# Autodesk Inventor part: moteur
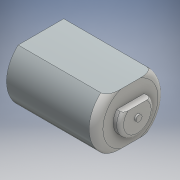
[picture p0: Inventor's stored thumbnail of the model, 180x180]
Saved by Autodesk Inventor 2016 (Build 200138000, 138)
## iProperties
Created: 2018-03
Part Number: moteur
Material: Générique
Document SubType Name: Modeling
Designer: Bruno
Density: 1 g/cm^3
Appearance: Zinc
Author: Bruno
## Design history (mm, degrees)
sketch "Esquisse1"
  geometry: C1 r 10 at (0, 0); 1 further point
  constraints: 1 centre point, 1 coincident
  dimensions: "d0" = 20 diameter of C1
extrude "Extrusion1" new body sketch "Esquisse1" distance "d1" = 21; taper "d2" = 0 deg
sketch "Esquisse2"
  geometry: L1 (-7.5, 6.614)-(-7.5, -7.599); L2 (7.5, 6.614)-(7.5, -6.614); L3 (-7.5, 6.614)-(-12.046, 9.746); L4 (-12.046, 9.746)-(-12.489, -11.62); L5 (-12.489, -11.62)-(-7.5, -7.599); L6 (7.5, 6.614)-(13.035, 8.656); L7 (13.035, 8.656)-(13.254, -8.986); L8 (13.254, -8.986)-(7.5, -6.614); A1 r 10 centre (0, 0) between (-7.5, 6.614) and (7.5, 6.614) reference; 1 further point
  constraints: 16 end point, 3 point on circle, 2 vertical
  dimensions: "d3" = 7.5 distance from line of L1 point (0, 0); "d4" = 15 distance between parallel lines of L2 L1
extrude "Extrusion2" cut sketch "Esquisse2" distance "d5" = 21; taper "d6" = 0 deg
sketch "Esquisse3"
  geometry: L1 (-7.5, 6.614)-(-7.5, -6.614) reference; L2 (7.5, -6.614)-(7.5, 6.614) reference; L3 (-7.439, 6.591)-(-7.439, -6.591); L4 (7.439, -6.591)-(7.439, 6.591); A1 r 10 centre (0, 0) between (-7.5, -6.614) and (7.5, -6.614) reference; A2 r 10 centre (0, 0) between (7.5, 6.614) and (-7.5, 6.614) reference; A3 r 9.939 centre (0, 0) between (-7.439, -6.591) and (7.439, -6.591); A4 r 9.939 centre (0, 0) between (7.439, 6.591) and (-7.439, 6.591); 1 further point
  constraints: 4 end point, 4 point on circle, 2 centre point, 3 other
extrude "Extrusion3" join sketch "Esquisse3" distance "d7" = 5; taper "d8" = 0 deg
fillet "Congé1" dims "d9" = 2
sketch "Esquisse4"
  geometry: L1 (-3, 4)-(-3, -4); A1 r 5 centre (0, 0) between (-3, 4) and (-3, -4); 1 further point
  constraints: 2 end point, 2 point on circle, 1 centre point, 1 coincident, 1 vertical
  dimensions: "d10" = 10 diameter of A1; "d11" = 3 distance from line of point (0, 0) L1
extrude "Extrusion4" join sketch "Esquisse4" distance "d12" = 2; taper "d13" = 0 deg
fillet "Congé2" dims "d14" = 1
sketch "Esquisse5"
  geometry: C1 r 0.88 at (0, 0); 1 further point
  constraints: 1 centre point, 1 coincident
extrude "Extrusion5" join sketch "Esquisse5" distance "d15" = 0.5; taper "d16" = 0 deg
node "Solide1"
node "Boucle projetée1"
node "Boucle projetée2"
